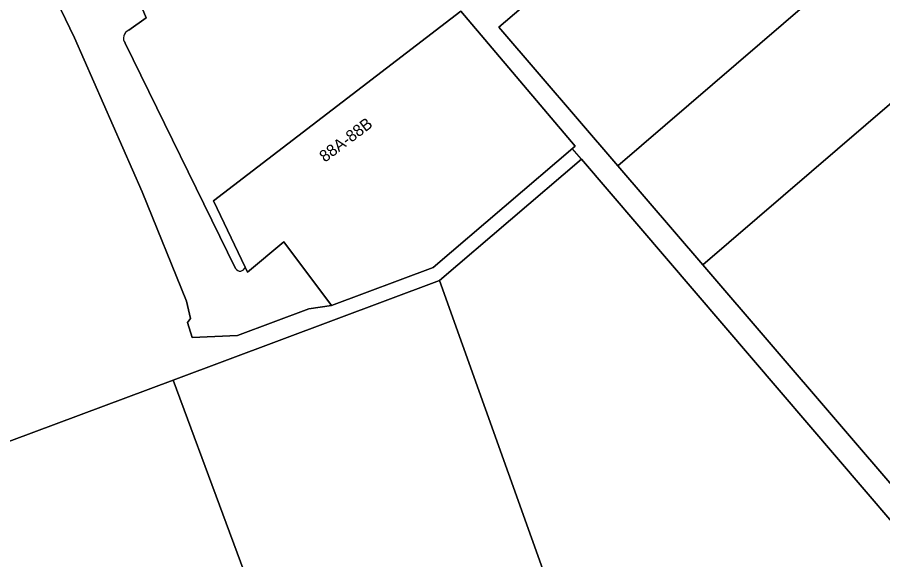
# Model space of a CAD drawing. Extents: x 162172 to 163187, y 382874 to 383685.
# Drawn here: x 162391 to 162464.8, y 383199.1 to 383245.3 of the extents above; entities that cross this region are included whole.
import ezdxf

# ---------------------------------------------------------------- set-up
doc = ezdxf.new("R2010")
doc.units = 0
for name, color, linetype in [('IMGEO_Erf', 7, 'Continuous'), ('IMGEO_Muur', 7, 'Continuous'), ('IMGEO_Pand', 7, 'Continuous'), ('IMGEO_Pand_nummerreeks', 7, 'Continuous'), ('IMGEO_Rijbaan_lokaal_open', 7, 'Continuous')]:
    doc.layers.add(name, color=color, linetype=linetype)

msp = doc.modelspace()

# ---------------------------------------------------------------- linework, layer by layer
at = {"layer": 'IMGEO_Erf'}
for points in [[(162370.478, 383201.768), (162404.26, 383214.377), (162426.965, 383222.853), (162439.076, 383233.212), (162468.068, 383199.324), (162469.633, 383200.663), (162466.572, 383204.228), (162449.417, 383224.206), (162442.165, 383232.652), (162432.032, 383244.453), (162438.509, 383250)], [(162410.393, 383223.994), (162407.685, 383229.67), (162428.769, 383245.828), (162438.517, 383234.328), (162426.429, 383223.977), (162417.764, 383220.743), (162415.818, 383220.435), (162409.749, 383218.187), (162405.876, 383218.005), (162405.477, 383219.277), (162405.733, 383219.619), (162405.386, 383221.106), (162401.619, 383230.434), (162395.828, 383243.563), (162392.733, 383250)], [(162399.993, 383250), (162401.954, 383245.27), (162400.458, 383244.217)], [(162400.147, 383243.089), (162409.573, 383223.892)]]:
    msp.add_lwpolyline(points, dxfattribs=at)
for centre, radius, start, end in [((162400.785, 383243.52), 0.77, 115.15155, 214.0204), ((162409.962, 383224.113), 0.447, 209.58354, 344.59769)]:
    msp.add_arc(centre, radius, start, end, dxfattribs=at)
at = {"layer": 'IMGEO_Muur'}
msp.add_lwpolyline([(162439.076, 383233.212), (162438.289, 383234.132)], dxfattribs=at)
at = {"layer": 'IMGEO_Pand'}
for points in [[(162480.072, 383265.207), (162467.752, 383279.555), (162463.597, 383276.001), (162460.487, 383273.341), (162459.518, 383273.224), (162457.316, 383275.789), (162457.627, 383276.056), (162456.845, 383276.966), (162453.052, 383273.709), (162446.489, 383268.073), (162452.05, 383261.596), (162438.509, 383250), (162432.032, 383244.453), (162442.165, 383232.652), (162462.365, 383250)], [(162480.072, 383265.207), (162462.365, 383250), (162442.165, 383232.652), (162449.417, 383224.206), (162479.441, 383250), (162499.12, 383266.906), (162491.908, 383275.345)], [(162417.764, 383220.743), (162426.429, 383223.977), (162438.517, 383234.328), (162428.769, 383245.828), (162407.685, 383229.67), (162410.393, 383223.994), (162410.591, 383223.58), (162413.696, 383226.166)], [(162426.965, 383222.853), (162438.744, 383189.954), (162448.368, 383193.535), (162449.067, 383191.615), (162468.265, 383198.796), (162468.192, 383198.991), (162468.068, 383199.324), (162439.076, 383233.212)], [(162426.965, 383222.853), (162404.26, 383214.377), (162416.948, 383180.088), (162417.081, 383179.732), (162435.488, 383186.528), (162434.779, 383188.479), (162438.744, 383189.954)], [(162386.314, 383136.041), (162415.944, 383147.093), (162417.844, 383147.826), (162410.672, 383167.051), (162409.86, 383166.738), (162408.565, 383170.144), (162409.362, 383170.441), (162414.958, 383172.527), (162412.841, 383178.088), (162412.51, 383178.958), (162415.912, 383180.219), (162416.23, 383179.355), (162417.081, 383179.732), (162416.948, 383180.088), (162404.26, 383214.377), (162370.478, 383201.768), (162383.174, 383167.656), (162375.57, 383164.802)]]:
    msp.add_lwpolyline(points, close=True, dxfattribs=at)
msp.add_lwpolyline([(162479.441, 383250), (162449.417, 383224.206), (162466.572, 383204.228)], dxfattribs=at)
at = {"layer": 'IMGEO_Rijbaan_lokaal_open'}
for points in [[(162400.458, 383244.217), (162401.954, 383245.27), (162399.993, 383250), (162397.916, 383255.011), (162396.159, 383254.208), (162393.364, 383260.33), (162394.025, 383260.635)], [(162384.074, 383255.297), (162386.337, 383250.936), (162390.549, 383254.542), (162392.733, 383250), (162395.828, 383243.563), (162401.619, 383230.434), (162405.386, 383221.106), (162405.733, 383219.619), (162405.477, 383219.277), (162405.876, 383218.005), (162409.749, 383218.187), (162415.818, 383220.435), (162417.764, 383220.743), (162413.696, 383226.166), (162410.591, 383223.58), (162410.393, 383223.994)], [(162409.573, 383223.892), (162400.147, 383243.089)]]:
    msp.add_lwpolyline(points, dxfattribs=at)
for centre, radius, start, end in [((162400.785, 383243.52), 0.77, 115.15155, 214.0204), ((162409.962, 383224.113), 0.447, 209.58354, 344.59769)]:
    msp.add_arc(centre, radius, start, end, dxfattribs=at)

# ---------------------------------------------------------------- texts
at = {"layer": 'IMGEO_Pand_nummerreeks'}
msp.add_text('88A-88B', height=1, rotation=37.00896, dxfattribs=at).set_placement((162417.188, 383232.9))

doc.saveas('drawing.dxf')
